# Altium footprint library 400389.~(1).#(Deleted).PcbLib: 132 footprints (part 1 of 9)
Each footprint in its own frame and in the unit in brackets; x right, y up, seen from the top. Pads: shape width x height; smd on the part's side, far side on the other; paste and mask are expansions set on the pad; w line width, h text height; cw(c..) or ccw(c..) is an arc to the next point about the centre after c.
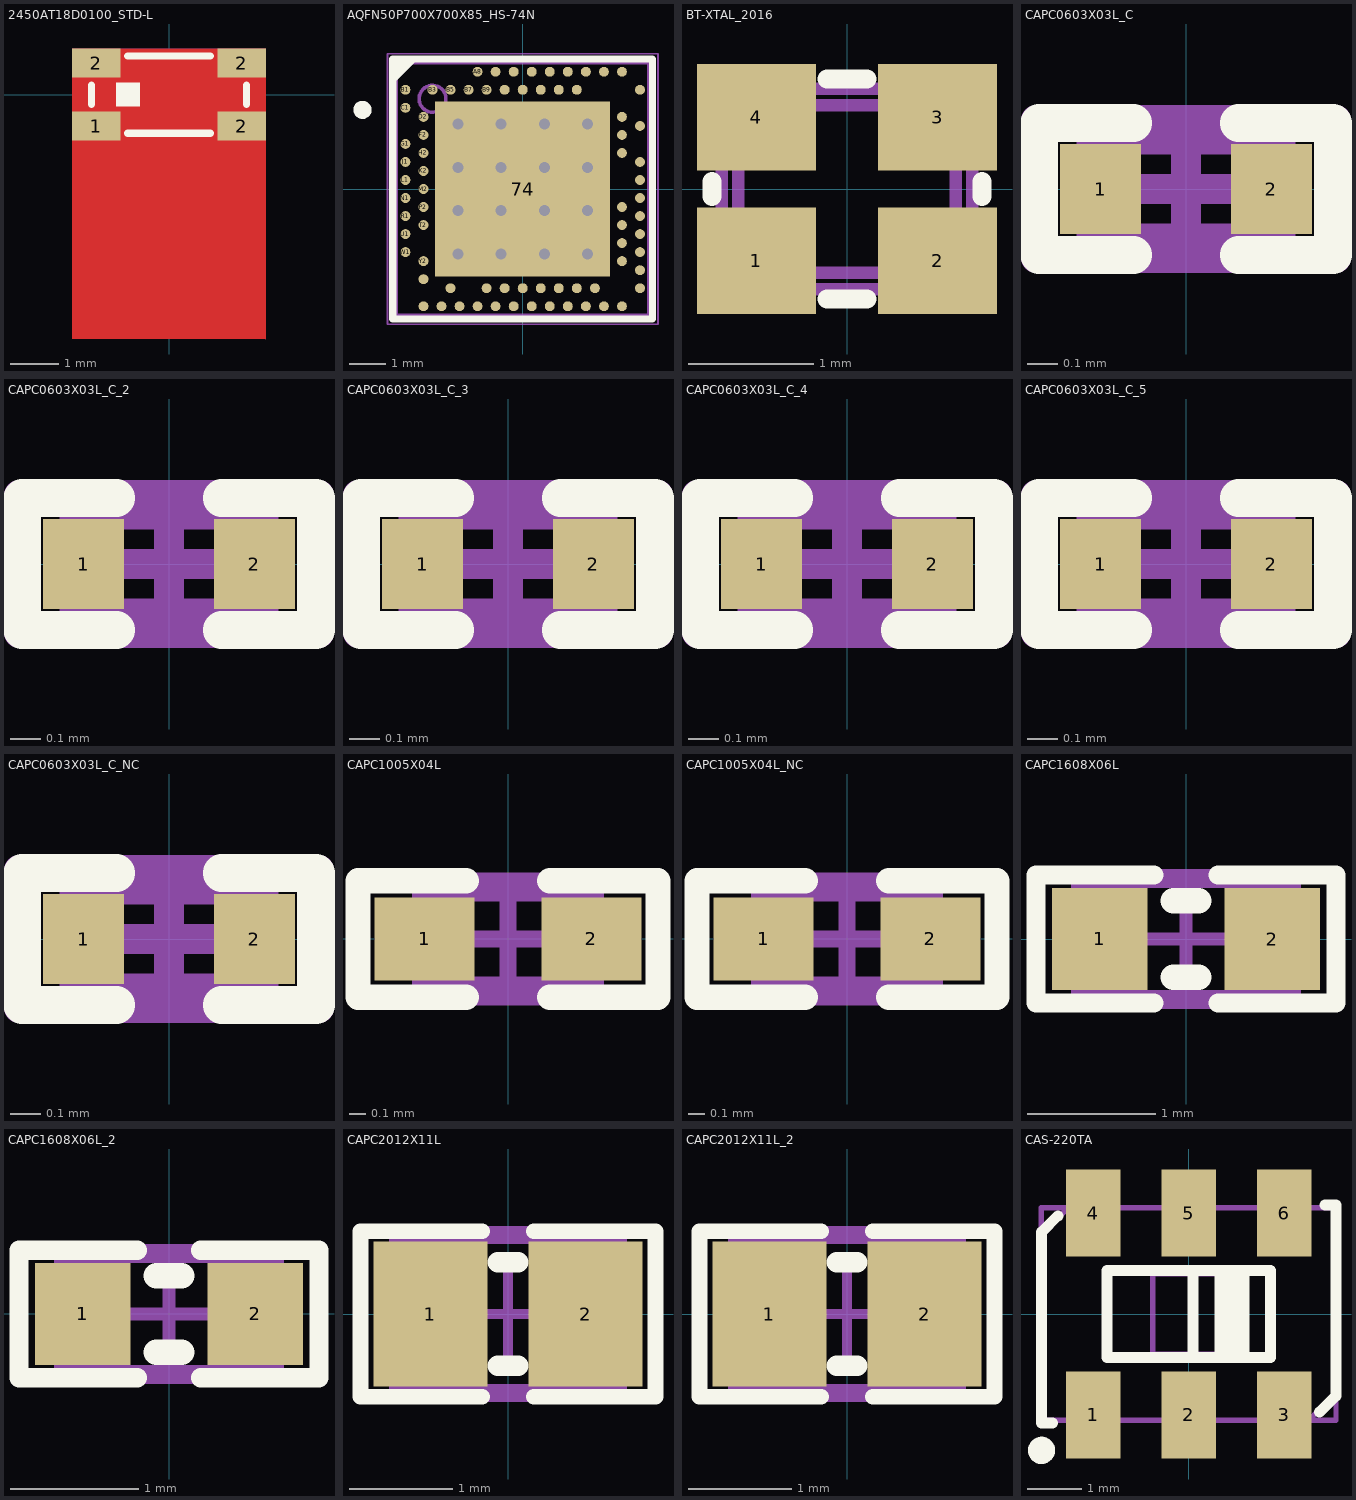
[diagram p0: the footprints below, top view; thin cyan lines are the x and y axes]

## 2450AT18D0100_STD-L [mm]
pads (4):
  rect 1x0.6 smd mask+0.051: 1(-1.5,-0.65) 2(-1.5,0.65) 2(1.5,-0.65) 2(1.5,0.65)
Top Layer:
  pour cut-out: -2,-5.05 -2,0.95 2,0.95 2,-5.05
Bottom Layer:
  pour cut-out: -2,-5.05 -2,0.95 2,0.95 2,-5.05
Top Overlay:
  rectangle: -1.1,-0.25 -0.6,0.25
  lines w0.15: -1.6,-0.2 -1.6,0.2 ; -0.85,-0.8 0.85,-0.8 ; -0.85,0.8 0.85,0.8 ; 1.6,-0.2 1.6,0.2
Mechanical 7:
  lines w0.1: -1.6,-0.5 -1.1,-0.5 -1.1,-0.8 ; -1.6,0.5 -1.1,0.5 -1.1,0.8 ; 1.1,-0.8 1.1,-0.5 1.6,-0.5 ; 1.1,0.8 1.1,0.5 1.6,0.5 ; -1.6,-0.8 -1.6,0.8 1.6,0.8 1.6,-0.8 -1.6,-0.8 ; -1.106,-0.247 -0.607,-0.247 -0.607,0.252 -1.106,0.252 -1.106,-0.247
  text ".Designator" at -0.4,-0.2 h0.38
3D body: height 1.2, standoff 0.01, extent -1.099,-0.25 -0.6,0.25
3D body: height 1.2, standoff 0, extent -1.605,-0.805 -1.105,-0.505
3D body: height 1.2, standoff 0, extent -1.6,-0.8 1.6,0.8
3D body: height 1.2, standoff 0, extent 1.105,0.505 1.605,0.805
3D body: height 1.2, standoff 0, extent 1.105,-0.805 1.605,-0.505
3D body: height 1.2, standoff 0, extent -1.605,0.505 -1.105,0.805

## AQFN50P700X700X85_HS-74N [mm]
pads (90):
  rect 4.85x4.85 smd paste-5 mask+0.05: 74(0,0)
  round 0.275 smd paste+0.012 mask+0.05: A8(-1.25,3.25) A10(-0.75,3.25) A12(-0.25,3.25) A14(0.25,3.25) A16(0.75,3.25) A18(1.25,3.25) A20(1.75,3.25) A22(2.25,3.25) A23(2.75,3.25) AA24(3.25,-2.25) AB2(-2.75,-2.5) AC5(-2,-2.75) AC9(-1,-2.75) AC11(-0.5,-2.75) AC13(0,-2.75) AC15(0.5,-2.75) AC17(1,-2.75) AC19(1.5,-2.75) AC21(2,-2.75) AC24(3.25,-2.75) AD2(-2.75,-3.25) AD4(-2.25,-3.25) AD6(-1.75,-3.25) AD8(-1.25,-3.25) AD10(-0.75,-3.25) AD12(-0.25,-3.25) AD14(0.25,-3.25) AD16(0.75,-3.25) AD18(1.25,-3.25) AD20(1.75,-3.25) AD22(2.25,-3.25) AD23(2.75,-3.25) B1(-3.25,2.75) B3(-2.5,2.75) B5(-2,2.75) B7(-1.5,2.75) B9(-1,2.75) B11(-0.5,2.75) B13(0,2.75) B15(0.5,2.75) B17(1,2.75) B19(1.5,2.75) B24(3.25,2.75) C1(-3.25,2.25) D2(-2.75,2) D23(2.75,2) E24(3.25,1.75) F2(-2.75,1.5) F23(2.75,1.5) G1(-3.25,1.25) H2(-2.75,1) H23(2.75,1) J1(-3.25,0.75) J24(3.25,0.75) K2(-2.75,0.5) L1(-3.25,0.25) L24(3.25,0.25) M2(-2.75,0) N1(-3.25,-0.25) N24(3.25,-0.25) P2(-2.75,-0.5) P23(2.75,-0.5) R1(-3.25,-0.75) R24(3.25,-0.75) T2(-2.75,-1) T23(2.75,-1) U1(-3.25,-1.25) U24(3.25,-1.25) V23(2.75,-1.5) W1(-3.25,-1.75) W24(3.25,-1.75) Y2(-2.75,-2) Y23(2.75,-2)
  rrect50% 0.94x0.94 on Top Paste: ""(-1.71,-1.71) ""(-1.71,-0.57) ""(-1.71,0.57) ""(-1.71,1.71) ""(-0.57,-1.71) ""(-0.57,-0.57) ""(-0.57,0.57) ""(-0.57,1.71) ""(0.57,-1.71) ""(0.57,-0.57) ""(0.57,0.57) ""(0.57,1.71) ""(1.71,-1.71) ""(1.71,-0.57) ""(1.71,0.57) ""(1.71,1.71)
via 1.8,-1.8 diameter 0.61 hole 0.305
via 0.6,-1.8 diameter 0.61 hole 0.305
via -0.6,-1.8 diameter 0.61 hole 0.305
via -1.8,-1.8 diameter 0.61 hole 0.305
via 1.8,-0.6 diameter 0.61 hole 0.305
via 0.6,-0.6 diameter 0.61 hole 0.305
via -0.6,-0.6 diameter 0.61 hole 0.305
via -1.8,-0.6 diameter 0.61 hole 0.305
via 1.8,0.6 diameter 0.61 hole 0.305
via 0.6,0.6 diameter 0.61 hole 0.305
via -0.6,0.6 diameter 0.61 hole 0.305
via -1.8,0.6 diameter 0.61 hole 0.305
via 1.8,1.8 diameter 0.61 hole 0.305
via 0.6,1.8 diameter 0.61 hole 0.305
via -0.6,1.8 diameter 0.61 hole 0.305
via -1.8,1.8 diameter 0.61 hole 0.305
Top Overlay:
  circle w0.25: c-4.44,2.194 r0.125
  region: -3,3.5 -3.5,3 -3.5,3.5
  lines w0.2: -3.6,-3.6 3.6,-3.6 3.6,3.6 -3.6,3.6 -3.6,-3.6
Mechanical 7:
  circle w0.1: c-2.5,2.5 r0.373
  lines w0.1: -3.5,-3.5 -3.5,3.5 3.5,3.5 3.5,-3.5 -3.5,-3.5
  text ".Designator" at -0.75,-0.25 h0.38
Mechanical 15:
  lines w0.05: -3.75,-3.75 3.75,-3.75 3.75,3.75 -3.75,3.75 -3.75,-3.75
  lines w0.1: -0.5,0 0.5,0 ; 0,-0.5 0,0.5
3D body "aQFN-73.step": height 0.87, standoff -0.03, extent -3.5,-3.5 3.5,3.5

## BT-XTAL_2016 [mm]
pads (4):
  rect 0.95x0.85 smd: 1(-0.725,-0.575) 2(0.725,-0.575) 3(0.725,0.575) 4(-0.725,0.575)
Top Overlay:
  lines w0.152: -1.08,-0.06 -1.08,0.06 ; -0.16,-0.88 0.16,-0.88 ; -0.16,0.88 0.16,0.88 ; 1.08,-0.06 1.08,0.06
Mechanical 7:
  lines w0.1: -1,-0.7 cw(c-1,-0.8) -0.9,-0.8 0.9,-0.8 cw(c1,-0.8) 1,-0.7 1,0.7 cw(c1,0.8) 0.9,0.8 -0.9,0.8 cw(c-1,0.8) -1,0.7 -1,-0.7 ; -0.87,-0.57 ccw(c-0.77,-0.57) -0.77,-0.67 0.77,-0.67 ccw(c0.77,-0.57) 0.87,-0.57 0.87,0.57 ccw(c0.77,0.57) 0.77,0.67 -0.77,0.67 ccw(c-0.77,0.57) -0.87,0.57 -0.87,-0.57
  text ".Designator" at -0.7,-0.2 h0.38
3D body: height 0.56, standoff 0.15, extent -0.7,-0.65 0.7,0.65
3D body "User Library-GeyerElectronics_KX5.step": height 0.56, standoff 0, extent -1.05,-0.85 1.05,0.85

## CAPC0603X03L_C [mm]
pads (2):
  rect 0.27x0.3 smd mask+0.05: 1(-0.285,0) 2(0.285,0)
Top Overlay:
  lines w0.125: -0.175,-0.22 -0.49,-0.22 -0.49,0.22 -0.175,0.22 ; 0.175,-0.22 0.49,-0.22 0.49,0.22 0.175,0.22
Mechanical 7:
  lines w0.1: -0.315,-0.165 0.315,-0.165 0.315,0.165 -0.315,0.165 -0.315,-0.165
  text ".Designator" at -0.306,0.268 h0.3
Mechanical 15:
  lines w0.1: -0.165,0 0.165,0 ; 0,-0.165 0,0.165 ; -0.5,-0.23 0.5,-0.23 0.5,0.23 -0.5,0.23 -0.5,-0.23
3D body "User Library-0201(0603M) Cap.step": height 0.3, standoff -0.01, extent -0.305,-0.152 0.305,0.153

## CAPC0603X03L_C_2 [mm]
pads (2):
  rect 0.27x0.3 smd mask+0.05: 1(-0.285,0) 2(0.285,0)
Top Overlay:
  lines w0.125: -0.175,-0.22 -0.49,-0.22 -0.49,0.22 -0.175,0.22 ; 0.175,-0.22 0.49,-0.22 0.49,0.22 0.175,0.22
Mechanical 7:
  lines w0.1: -0.315,-0.165 -0.315,0.165 0.315,0.165 0.315,-0.165 -0.315,-0.165
  text ".Designator" at -0.306,0.268 h0.3
Mechanical 15:
  lines w0.1: -0.165,0 0.165,0 ; 0,-0.165 0,0.165 ; -0.5,-0.23 -0.5,0.23 0.5,0.23 0.5,-0.23 -0.5,-0.23
3D body "User Library-0201(0603M) Cap.step": height 0.3, standoff -0.01, extent -0.305,-0.152 0.305,0.153

## CAPC0603X03L_C_3 [mm]
pads (2):
  rect 0.27x0.3 smd mask+0.05: 1(-0.285,0) 2(0.285,0)
Top Overlay:
  lines w0.125: -0.175,-0.22 -0.49,-0.22 -0.49,0.22 -0.175,0.22 ; 0.175,-0.22 0.49,-0.22 0.49,0.22 0.175,0.22
Mechanical 7:
  lines w0.1: -0.315,-0.165 -0.315,0.165 0.315,0.165 0.315,-0.165 -0.315,-0.165
  text ".Designator" at -0.306,0.268 h0.3
Mechanical 15:
  lines w0.1: -0.165,0 0.165,0 ; 0,-0.165 0,0.165 ; -0.5,-0.23 -0.5,0.23 0.5,0.23 0.5,-0.23 -0.5,-0.23
3D body "User Library-0201(0603M) Cap.step": height 0.3, standoff -0.01, extent -0.305,-0.152 0.305,0.153

## CAPC0603X03L_C_4 [mm]
pads (2):
  rect 0.27x0.3 smd mask+0.05: 1(-0.285,0) 2(0.285,0)
Top Overlay:
  lines w0.125: -0.175,-0.22 -0.49,-0.22 -0.49,0.22 -0.175,0.22 ; 0.175,-0.22 0.49,-0.22 0.49,0.22 0.175,0.22
Mechanical 7:
  lines w0.1: -0.315,-0.165 -0.315,0.165 0.315,0.165 0.315,-0.165 -0.315,-0.165
  text ".Designator" at -0.306,0.268 h0.3
Mechanical 15:
  lines w0.1: -0.165,0 0.165,0 ; 0,-0.165 0,0.165 ; -0.5,-0.23 -0.5,0.23 0.5,0.23 0.5,-0.23 -0.5,-0.23
3D body "User Library-0201(0603M) Cap.step": height 0.3, standoff -0.01, extent -0.305,-0.152 0.305,0.153

## CAPC0603X03L_C_5 [mm]
pads (2):
  rect 0.27x0.3 smd mask+0.05: 1(-0.285,0) 2(0.285,0)
Top Overlay:
  lines w0.125: -0.175,-0.22 -0.49,-0.22 -0.49,0.22 -0.175,0.22 ; 0.175,-0.22 0.49,-0.22 0.49,0.22 0.175,0.22
Mechanical 7:
  lines w0.1: -0.315,-0.165 -0.315,0.165 0.315,0.165 0.315,-0.165 -0.315,-0.165
  text ".Designator" at -0.306,0.268 h0.3
Mechanical 15:
  lines w0.1: -0.165,0 0.165,0 ; 0,-0.165 0,0.165 ; -0.5,-0.23 -0.5,0.23 0.5,0.23 0.5,-0.23 -0.5,-0.23
3D body "User Library-0201(0603M) Cap.step": height 0.3, standoff -0.01, extent -0.305,-0.152 0.305,0.153

## CAPC0603X03L_C_NC [mm]
pads (2):
  rect 0.27x0.3 smd mask+0.05: 1(-0.285,0) 2(0.285,0)
Top Overlay:
  lines w0.125: -0.175,-0.22 -0.49,-0.22 -0.49,0.22 -0.175,0.22 ; 0.175,-0.22 0.49,-0.22 0.49,0.22 0.175,0.22
Mechanical 7:
  lines w0.1: -0.315,-0.165 -0.315,0.165 0.315,0.165 0.315,-0.165 -0.315,-0.165
  text ".Designator" at -0.306,0.268 h0.3
Mechanical 15:
  lines w0.1: -0.165,0 0.165,0 ; 0,-0.165 0,0.165 ; -0.5,-0.23 -0.5,0.23 0.5,0.23 0.5,-0.23 -0.5,-0.23

## CAPC1005X04L [mm]
pads (2):
  rect 0.6x0.5 smd: 1(-0.5,0) 2(0.5,0)
Top Overlay:
  lines w0.152: -0.25,-0.35 -0.9,-0.35 -0.9,0.35 -0.25,0.35 ; 0.25,-0.35 0.9,-0.35 0.9,0.35 0.25,0.35
Mechanical 7:
  lines w0.1: -0.525,-0.275 0.525,-0.275 0.525,0.275 -0.525,0.275 -0.525,-0.275
  text ".Designator" at -0.432,-0.152 h0.3
Mechanical 15:
  lines w0.1: -0.275,0 0.275,0 ; 0,-0.275 0,0.275 ; -0.9,-0.35 -0.9,0.35 0.9,0.35 0.9,-0.35 -0.9,-0.35
3D body "User Library-0402(1005M) Cap.step": height 0.5, standoff -0.01, extent -0.508,-0.254 0.508,0.254

## CAPC1005X04L_NC [mm]
pads (2):
  rect 0.6x0.5 smd: 1(-0.5,0) 2(0.5,0)
Top Overlay:
  lines w0.152: -0.25,-0.35 -0.9,-0.35 -0.9,0.35 -0.25,0.35 ; 0.25,-0.35 0.9,-0.35 0.9,0.35 0.25,0.35
Mechanical 7:
  lines w0.1: -0.525,-0.275 -0.525,0.275 0.525,0.275 0.525,-0.275 -0.525,-0.275
  text ".Designator" at -0.432,-0.152 h0.3
Mechanical 15:
  lines w0.1: -0.275,0 0.275,0 ; 0,-0.275 0,0.275 ; -0.9,-0.35 0.9,-0.35 0.9,0.35 -0.9,0.35 -0.9,-0.35

## CAPC1608X06L [mm]
pads (2):
  rect 0.75x0.8 smd: 1(-0.675,0) 2(0.675,0)
Top Overlay:
  lines w0.15: -0.25,-0.5 -1.175,-0.5 -1.175,0.5 -0.25,0.5 ; 0.25,-0.5 1.175,-0.5 1.175,0.5 0.25,0.5
  lines w0.2: -0.1,-0.3 0.1,-0.3 ; -0.1,0.3 0.1,0.3
Mechanical 7:
  lines w0.1: -0.85,-0.45 0.85,-0.45 0.85,0.45 -0.85,0.45 -0.85,-0.45
  text ".Designator" at -0.685,-0.142 h0.38
Mechanical 15:
  lines w0.1: -0.45,0 0.45,0 ; 0,-0.45 0,0.45 ; -1.175,-0.5 -1.175,0.5 1.175,0.5 1.175,-0.5 -1.175,-0.5
3D body "User Library-Chip Capacitor 0603.step": height 0.8, standoff 0, extent -0.8,-0.43 0.8,0.43

## CAPC1608X06L_2 [mm]
pads (2):
  rect 0.75x0.8 smd: 1(-0.675,0) 2(0.675,0)
Top Overlay:
  lines w0.152: -0.25,-0.5 -1.175,-0.5 -1.175,0.5 -0.25,0.5 ; 0.25,-0.5 1.175,-0.5 1.175,0.5 0.25,0.5
  lines w0.2: -0.1,-0.3 0.1,-0.3 ; -0.1,0.3 0.1,0.3
Mechanical 7:
  lines w0.1: -0.85,-0.45 -0.85,0.45 0.85,0.45 0.85,-0.45 -0.85,-0.45
  text ".Designator" at -0.711,-0.152 h0.3
Mechanical 15:
  lines w0.1: -0.45,0 0.45,0 ; 0,-0.45 0,0.45 ; -1.175,-0.5 1.175,-0.5 1.175,0.5 -1.175,0.5 -1.175,-0.5
3D body "User Library-Chip Capacitor 0603.step": height 0.8, standoff 0, extent -0.8,-0.43 0.8,0.43

## CAPC2012X11L [mm]
pads (2):
  rect 1.1x1.4 smd: 1(-0.75,0) 2(0.75,0)
Top Overlay:
  lines w0.152: -0.25,-0.8 -1.425,-0.8 -1.425,0.8 -0.25,0.8 ; 0.25,-0.8 1.425,-0.8 1.425,0.8 0.25,0.8
  lines w0.2: -0.1,-0.5 0.1,-0.5 ; -0.1,0.5 0.1,0.5
Mechanical 7:
  lines w0.1: -1.1,-0.725 -1.1,0.725 1.1,0.725 1.1,-0.725 -1.1,-0.725
  text ".Designator" at -0.711,-0.152 h0.3
Mechanical 15:
  lines w0.1: -0.5,0 0.5,0 ; 0,-0.5 0,0.5 ; -1.425,-0.8 -1.425,0.8 1.425,0.8 1.425,-0.8 -1.425,-0.8
3D body "SW3dPS-0805 SMD Capacitor.STEP": height 0.77, standoff -0.01, extent -1,-0.625 1,0.625

## CAPC2012X11L_2 [mm]
pads (2):
  rect 1.1x1.4 smd: 1(-0.75,0) 2(0.75,0)
Top Overlay:
  lines w0.152: -0.25,-0.8 -1.425,-0.8 -1.425,0.8 -0.25,0.8 ; 0.25,-0.8 1.425,-0.8 1.425,0.8 0.25,0.8
  lines w0.2: -0.1,-0.5 0.1,-0.5 ; -0.1,0.5 0.1,0.5
Mechanical 7:
  lines w0.1: -1.1,-0.725 -1.1,0.725 1.1,0.725 1.1,-0.725 -1.1,-0.725
  text ".Designator" at -0.711,-0.152 h0.3
Mechanical 15:
  lines w0.1: -0.5,0 0.5,0 ; 0,-0.5 0,0.5 ; -1.425,-0.8 -1.425,0.8 1.425,0.8 1.425,-0.8 -1.425,-0.8
3D body "SW3dPS-0805 SMD Capacitor.STEP": height 0.77, standoff -0.01, extent -1,-0.625 1,0.625

## CAS-220TA [mm]
pads (6):
  rect 1x1.6 smd: 1(-1.75,-1.85) 2(0,-1.85) 3(1.75,-1.85) 4(-1.75,1.85) 5(0,1.85) 6(1.75,1.85)
Top Overlay:
  circle w0.3: c-2.7,-2.5 r0.1
  rectangle: 0.47,-0.8 1.11,0.8
  lines w0.2: -2.5,-2 -2.7,-2 -2.7,1.5 -2.4,1.8 ; 0.08,-0.8 0.08,0.8 ; 2.4,-1.8 2.7,-1.5 2.7,2 2.5,2 ; -1.5,-0.8 -1.5,0.8 1.5,0.8 1.5,-0.8 -1.5,-0.8
Mechanical 7:
  lines w0.1: -2.7,1.45 -2.2,1.95 ; -2.05,-1.95 -2.05,-2.1 -1.45,-2.1 -1.45,-1.95 ; -2.05,1.95 -2.05,2.1 -1.45,2.1 -1.45,1.95 ; -0.3,-1.95 -0.3,-2.1 0.3,-2.1 0.3,-1.95 ; -0.3,1.95 -0.3,2.1 0.3,2.1 0.3,1.95 ; 0.06,-0.738 0.06,0.738 ; 1.45,-1.95 1.45,-2.1 2.05,-2.1 2.05,-1.95 ; 1.45,1.95 1.45,2.1 2.05,2.1 2.05,1.95 ; 2.2,-1.95 2.7,-1.45 ; -1.5,-0.828 -0.66,-0.738 ; -1.5,-0.828 1.5,-0.828 ; -1.5,-0.828 -1.5,0.828 ; -1.5,0.828 1.5,0.828 ; -1.5,0.828 -0.66,0.738 ; -0.66,-0.738 -0.66,0.738 ; -0.66,-0.738 0.66,-0.738 ; -0.66,0.738 0.66,0.738 ; 0.66,-0.738 1.5,-0.828 ; 0.66,-0.738 0.66,0.738 ; 0.66,0.738 1.5,0.828 ; 1.5,-0.828 1.5,0.828 ; -2.7,-1.95 -2.7,1.95 2.7,1.95 2.7,-1.95 -2.7,-1.95
  text ".Designator" at -0.775,1.075 h0.38
3D body: height 2.51, standoff 2.5, extent -1.497,-1.879 -0.9,-1.28
3D body: height 2.22, standoff 2.2, extent 0.08,-0.8 1.5,0.8
3D body: height 2.5, standoff 2.22, extent 0.47,-0.8 1.11,0.8
3D body: height 0.15, standoff 0, extent 1.45,1.305 2.05,2.005
3D body: height 1.2, standoff 0, extent 1.45,2.005 2.05,2.155
3D body: height 0.15, standoff 0, extent -2.05,1.305 -1.45,2.005
3D body: height 1.2, standoff 0, extent -2.05,2.005 -1.45,2.155
3D body: height 0.15, standoff 0, extent -0.3,-2.005 0.3,-1.305
3D body: height 1.2, standoff 0, extent -0.3,-2.155 0.3,-2.005
3D body: height 2.2, standoff 0.15, extent -2.7,-2 2.7,2
3D body: height 2.5, standoff 2.2, extent -2.7,0.8 2.7,2
3D body: height 2.5, standoff 2.2, extent -2.7,-1.15 -1.5,1.15
3D body: height 2.5, standoff 2.2, extent 1.5,-1.15 2.7,1.15
3D body: height 1.2, standoff 0, extent -2.05,-2.155 -1.45,-2.005
3D body: height 1.2, standoff 0, extent 1.45,-2.155 2.05,-2.005
3D body: height 1.2, standoff 0, extent -0.3,2.005 0.3,2.155
3D body: height 0.15, standoff 0, extent -2.05,-2.005 -1.45,-1.305
3D body: height 0.15, standoff 0, extent 1.45,-2.005 2.05,-1.305
3D body: height 0.15, standoff 0, extent -0.3,1.305 0.3,2.005
3D body: height 2.5, standoff 2.2, extent -2.7,-2 2.7,-0.8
